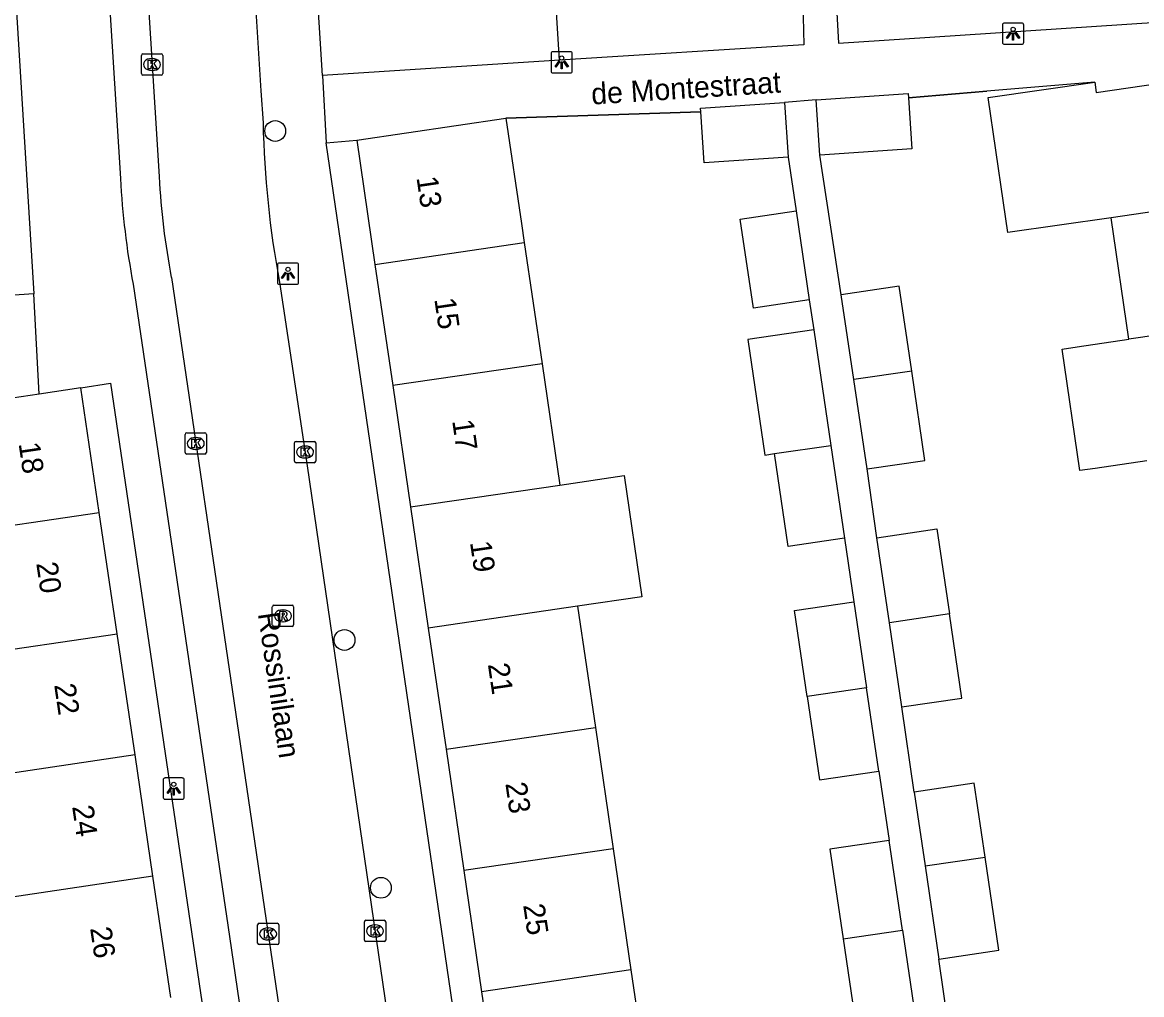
# Model space of a CAD drawing. Extents: x 159053 to 160041, y 380450 to 381422.
# Drawn here: x 159553.7 to 159606.3, y 381083.5 to 381129.1 of the extents above; entities that cross this region are included whole.
import ezdxf

# ---------------------------------------------------------------- set-up
doc = ezdxf.new("R2010")
doc.units = 0
for name, color, linetype in [('IMGEO_Boom', 7, 'Continuous'), ('IMGEO_Groenvoorziening', 7, 'Continuous'), ('IMGEO_Kolk', 7, 'Continuous'), ('IMGEO_Lichtpunt', 7, 'Continuous'), ('IMGEO_Muur', 7, 'Continuous'), ('IMGEO_Openbare_ruimte_label', 7, 'Continuous'), ('IMGEO_Pand', 7, 'Continuous'), ('IMGEO_Pand_nummerreeks', 7, 'Continuous'), ('IMGEO_Rijbaan_lokaal_open', 7, 'Continuous'), ('IMGEO_Rioolput', 7, 'Continuous'), ('IMGEO_Voetpad_op_trap', 7, 'Continuous'), ('IMGEO_Voetpad_open', 7, 'Continuous')]:
    doc.layers.add(name, color=color, linetype=linetype)

msp = doc.modelspace()

# ---------------------------------------------------------------- linework, layer by layer
at = {"layer": 'IMGEO_Boom'}
for centre in [(159565.58, 381124.031), (159568.834, 381100.135), (159570.545, 381088.501)]:
    msp.add_circle(centre, 0.489, dxfattribs=at)
at = {"layer": 'IMGEO_Groenvoorziening'}
msp.add_lwpolyline([(159578.93, 381127.348), (159578.726, 381130.611)], dxfattribs=at)
at = {"layer": 'IMGEO_Kolk'}
for p, q in [((159559.294, 381126.726), (159559.294, 381127.578)), ((159559.369, 381127.652), (159560.221, 381127.652)), ((159559.782, 381127.432), (159559.807, 381127.432)), ((159560.295, 381127.578), (159560.295, 381126.726)), ((159559.805, 381126.872), (159559.78, 381126.872)), ((159560.221, 381126.652), (159559.369, 381126.652)), ((159561.348, 381108.936), (159561.348, 381109.788)), ((159561.423, 381109.862), (159562.275, 381109.862)), ((159561.836, 381109.642), (159561.861, 381109.642)), ((159562.349, 381109.788), (159562.349, 381108.936)), ((159566.557, 381109.458), (159567.409, 381109.458)), ((159561.859, 381109.082), (159561.834, 381109.082)), ((159566.482, 381108.532), (159566.482, 381109.384)), ((159566.97, 381109.238), (159566.995, 381109.238)), ((159567.483, 381109.384), (159567.483, 381108.532)), ((159562.275, 381108.862), (159561.423, 381108.862)), ((159567.409, 381108.458), (159566.557, 381108.458)), ((159566.993, 381108.678), (159566.968, 381108.678)), ((159564.824, 381086.833), (159565.676, 381086.833)), ((159569.769, 381086.048), (159569.769, 381086.9)), ((159569.844, 381086.974), (159570.696, 381086.974)), ((159570.77, 381086.9), (159570.77, 381086.048)), ((159564.749, 381085.907), (159564.749, 381086.759)), ((159565.237, 381086.613), (159565.262, 381086.613)), ((159565.75, 381086.759), (159565.75, 381085.907)), ((159570.257, 381086.754), (159570.282, 381086.754)), ((159565.676, 381085.833), (159564.824, 381085.833)), ((159565.26, 381086.053), (159565.235, 381086.053)), ((159570.696, 381085.974), (159569.844, 381085.974)), ((159570.28, 381086.194), (159570.255, 381086.194))]:
    msp.add_line(p, q, dxfattribs=at)
for points in [[(159559.294, 381126.726), (159559.294, 381127.578)], [(159559.369, 381127.652), (159560.221, 381127.652)], [(159559.615, 381127.352), (159559.738, 381127.352), (159559.738, 381127.201), (159559.868, 381127.352), (159560.032, 381127.352), (159559.886, 381127.201), (159560.039, 381126.952), (159559.887, 381126.952), (159559.802, 381127.116), (159559.738, 381127.049), (159559.738, 381126.952), (159559.615, 381126.952), (159559.615, 381127.352)], [(159560.295, 381127.578), (159560.295, 381126.726)], [(159560.221, 381126.652), (159559.369, 381126.652)], [(159561.348, 381108.936), (159561.348, 381109.788)], [(159561.423, 381109.862), (159562.275, 381109.862)], [(159561.669, 381109.562), (159561.792, 381109.562), (159561.792, 381109.411), (159561.922, 381109.562), (159562.086, 381109.562), (159561.94, 381109.411), (159562.093, 381109.162), (159561.941, 381109.162), (159561.856, 381109.326), (159561.792, 381109.259), (159561.792, 381109.162), (159561.669, 381109.162), (159561.669, 381109.562)], [(159562.349, 381109.788), (159562.349, 381108.936)], [(159566.557, 381109.458), (159567.409, 381109.458)], [(159566.482, 381108.532), (159566.482, 381109.384)], [(159566.803, 381109.158), (159566.926, 381109.158), (159566.926, 381109.007), (159567.056, 381109.158), (159567.22, 381109.158), (159567.074, 381109.007), (159567.227, 381108.758), (159567.075, 381108.758), (159566.99, 381108.922), (159566.926, 381108.855), (159566.926, 381108.758), (159566.803, 381108.758), (159566.803, 381109.158)], [(159567.483, 381109.384), (159567.483, 381108.532)], [(159562.275, 381108.862), (159561.423, 381108.862)], [(159567.409, 381108.458), (159566.557, 381108.458)], [(159564.824, 381086.833), (159565.676, 381086.833)], [(159569.769, 381086.048), (159569.769, 381086.9)], [(159569.844, 381086.974), (159570.696, 381086.974)], [(159570.77, 381086.9), (159570.77, 381086.048)], [(159564.749, 381085.907), (159564.749, 381086.759)], [(159565.07, 381086.533), (159565.193, 381086.533), (159565.193, 381086.382), (159565.323, 381086.533), (159565.487, 381086.533), (159565.341, 381086.382), (159565.494, 381086.133), (159565.342, 381086.133), (159565.257, 381086.297), (159565.193, 381086.23), (159565.193, 381086.133), (159565.07, 381086.133), (159565.07, 381086.533)], [(159565.75, 381086.759), (159565.75, 381085.907)], [(159570.09, 381086.674), (159570.213, 381086.674), (159570.213, 381086.523), (159570.343, 381086.674), (159570.507, 381086.674), (159570.361, 381086.523), (159570.514, 381086.274), (159570.362, 381086.274), (159570.277, 381086.438), (159570.213, 381086.371), (159570.213, 381086.274), (159570.09, 381086.274), (159570.09, 381086.674)], [(159565.676, 381085.833), (159564.824, 381085.833)], [(159570.696, 381085.974), (159569.844, 381085.974)]]:
    msp.add_lwpolyline(points, dxfattribs=at)
for centre, start, end in [((159559.371, 381127.576), 91.552, 178.448), ((159559.371, 381127.576), 91.552, 178.448), ((159560.219, 381127.576), 1.552, 88.448), ((159560.219, 381127.576), 1.552, 88.448), ((159559.371, 381126.728), 181.552, 268.448), ((159559.371, 381126.728), 181.552, 268.448), ((159560.219, 381126.728), 271.552, 358.448), ((159560.219, 381126.728), 271.552, 358.448), ((159561.425, 381109.786), 91.552, 178.448), ((159561.425, 381109.786), 91.552, 178.448), ((159562.273, 381109.786), 1.552, 88.448), ((159562.273, 381109.786), 1.552, 88.448), ((159566.559, 381109.382), 91.552, 178.448), ((159566.559, 381109.382), 91.552, 178.448), ((159567.407, 381109.382), 1.552, 88.448), ((159567.407, 381109.382), 1.552, 88.448), ((159561.425, 381108.938), 181.552, 268.448), ((159561.425, 381108.938), 181.552, 268.448), ((159562.273, 381108.938), 271.552, 358.448), ((159562.273, 381108.938), 271.552, 358.448), ((159566.559, 381108.534), 181.552, 268.448), ((159566.559, 381108.534), 181.552, 268.448), ((159567.407, 381108.534), 271.552, 358.448), ((159567.407, 381108.534), 271.552, 358.448), ((159564.826, 381086.757), 91.552, 178.448), ((159564.826, 381086.757), 91.552, 178.448), ((159565.674, 381086.757), 1.552, 88.448), ((159565.674, 381086.757), 1.552, 88.448), ((159569.846, 381086.898), 91.552, 178.448), ((159569.846, 381086.898), 91.552, 178.448), ((159570.694, 381086.898), 1.552, 88.448), ((159570.694, 381086.898), 1.552, 88.448), ((159564.826, 381085.909), 181.552, 268.448), ((159564.826, 381085.909), 181.552, 268.448), ((159565.674, 381085.909), 271.552, 358.448), ((159565.674, 381085.909), 271.552, 358.448), ((159569.846, 381086.05), 181.552, 268.448), ((159569.846, 381086.05), 181.552, 268.448), ((159570.694, 381086.05), 271.552, 358.448), ((159570.694, 381086.05), 271.552, 358.448)]:
    msp.add_arc(centre, 0.0765, start, end, dxfattribs=at)
for centre, major_axis, ratio, start_param, end_param in [((159559.781, 381127.152), (-0.387, 0.002), 0.722429, 4.712389, 7.853982), ((159559.806, 381127.152), (-0.39, 0.002), 0.717154, 1.570796, 4.712389), ((159561.835, 381109.362), (-0.387, 0.002), 0.722429, 4.712389, 7.853982), ((159561.86, 381109.362), (-0.39, 0.002), 0.717154, 1.570796, 4.712389), ((159566.969, 381108.958), (-0.387, 0.002), 0.722429, 4.712389, 7.853982), ((159566.994, 381108.958), (-0.39, 0.002), 0.717154, 1.570796, 4.712389), ((159565.236, 381086.333), (-0.387, 0.002), 0.722429, 4.712389, 7.853982), ((159565.261, 381086.333), (-0.39, 0.002), 0.717154, 1.570796, 4.712389), ((159570.256, 381086.474), (-0.387, 0.002), 0.722429, 4.712389, 7.853982), ((159570.281, 381086.474), (-0.39, 0.002), 0.717154, 1.570796, 4.712389)]:
    msp.add_ellipse(centre, major_axis=major_axis, ratio=ratio, start_param=start_param, end_param=end_param, dxfattribs=at)
at = {"layer": 'IMGEO_Lichtpunt'}
for p, q in [((159599.743, 381129.004), (159599.743, 381128.197)), ((159599.743, 381129.004), (159599.743, 381128.197)), ((159600.645, 381129.099), (159599.837, 381129.099)), ((159600.645, 381129.099), (159599.837, 381129.099)), ((159600.739, 381128.197), (159600.739, 381129.004)), ((159600.739, 381128.197), (159600.739, 381129.004)), ((159599.837, 381128.103), (159600.645, 381128.103)), ((159599.837, 381128.103), (159600.645, 381128.103)), ((159578.538, 381127.658), (159578.538, 381126.851)), ((159578.538, 381127.658), (159578.538, 381126.851)), ((159579.44, 381127.753), (159578.632, 381127.753)), ((159579.44, 381127.753), (159578.632, 381127.753)), ((159579.534, 381126.851), (159579.534, 381127.658)), ((159579.534, 381126.851), (159579.534, 381127.658)), ((159578.632, 381126.757), (159579.44, 381126.757)), ((159578.632, 381126.757), (159579.44, 381126.757)), ((159566.584, 381117.831), (159565.776, 381117.831)), ((159566.584, 381117.831), (159565.776, 381117.831)), ((159565.682, 381117.736), (159565.682, 381116.929)), ((159565.682, 381117.736), (159565.682, 381116.929)), ((159566.678, 381116.929), (159566.678, 381117.736)), ((159566.678, 381116.929), (159566.678, 381117.736)), ((159565.776, 381116.835), (159566.584, 381116.835)), ((159565.776, 381116.835), (159566.584, 381116.835)), ((159561.216, 381093.655), (159560.408, 381093.655)), ((159561.216, 381093.655), (159560.408, 381093.655)), ((159560.314, 381093.56), (159560.314, 381092.753)), ((159560.314, 381093.56), (159560.314, 381092.753)), ((159561.31, 381092.753), (159561.31, 381093.56)), ((159561.31, 381092.753), (159561.31, 381093.56)), ((159560.408, 381092.659), (159561.216, 381092.659)), ((159560.408, 381092.659), (159561.216, 381092.659))]:
    msp.add_line(p, q, dxfattribs=at)
for points in [[(159600.117, 381128.668), (159600.156, 381128.64), (159599.968, 381128.378), (159599.93, 381128.405), (159600.117, 381128.668)], [(159600.219, 381128.62), (159600.266, 381128.62), (159600.266, 381128.298), (159600.219, 381128.298), (159600.219, 381128.62)], [(159600.329, 381128.64), (159600.367, 381128.667), (159600.554, 381128.405), (159600.515, 381128.377), (159600.329, 381128.64)], [(159578.912, 381127.322), (159578.951, 381127.294), (159578.763, 381127.032), (159578.725, 381127.059), (159578.912, 381127.322)], [(159579.124, 381127.294), (159579.162, 381127.321), (159579.349, 381127.059), (159579.31, 381127.031), (159579.124, 381127.294)], [(159579.014, 381127.274), (159579.061, 381127.274), (159579.061, 381126.952), (159579.014, 381126.952), (159579.014, 381127.274)], [(159566.056, 381117.4), (159566.095, 381117.372), (159565.907, 381117.11), (159565.869, 381117.137), (159566.056, 381117.4)], [(159566.158, 381117.352), (159566.205, 381117.352), (159566.205, 381117.03), (159566.158, 381117.03), (159566.158, 381117.352)], [(159566.268, 381117.372), (159566.306, 381117.399), (159566.493, 381117.137), (159566.454, 381117.109), (159566.268, 381117.372)], [(159560.688, 381093.224), (159560.727, 381093.196), (159560.539, 381092.934), (159560.501, 381092.961), (159560.688, 381093.224)], [(159560.79, 381093.176), (159560.837, 381093.176), (159560.837, 381092.854), (159560.79, 381092.854), (159560.79, 381093.176)], [(159560.9, 381093.196), (159560.938, 381093.223), (159561.125, 381092.961), (159561.086, 381092.933), (159560.9, 381093.196)]]:
    msp.add_lwpolyline(points, dxfattribs=at)
for centre in [(159600.242, 381128.802), (159579.037, 381127.456), (159566.181, 381117.534), (159560.813, 381093.358)]:
    msp.add_circle(centre, 0.0994, dxfattribs=at)
for centre, start, end in [((159599.837, 381129.004), 90, 180), ((159599.837, 381129.004), 90, 180), ((159600.645, 381129.004), 0, 90), ((159600.645, 381129.004), 0, 90), ((159599.837, 381128.197), 180, 270), ((159599.837, 381128.197), 180, 270), ((159600.645, 381128.197), 270, 0), ((159600.645, 381128.197), 270, 360), ((159578.632, 381127.658), 90, 180), ((159578.632, 381127.658), 90, 180), ((159579.44, 381127.658), 0, 90), ((159579.44, 381127.658), 0, 90), ((159578.632, 381126.851), 180, 270), ((159578.632, 381126.851), 180, 270), ((159579.44, 381126.851), 270, 0), ((159579.44, 381126.851), 270, 360), ((159565.776, 381117.736), 90, 180), ((159565.776, 381117.736), 90, 180), ((159566.584, 381117.736), 0, 90), ((159566.584, 381117.736), 0, 90), ((159565.776, 381116.929), 180, 270), ((159565.776, 381116.929), 180, 270), ((159566.584, 381116.929), 270, 0), ((159566.584, 381116.929), 270, 360), ((159560.408, 381093.56), 90, 180), ((159560.408, 381093.56), 90, 180), ((159561.216, 381093.56), 0, 90), ((159561.216, 381093.56), 0, 90), ((159560.408, 381092.753), 180, 270), ((159560.408, 381092.753), 180, 270), ((159561.216, 381092.753), 270, 0), ((159561.216, 381092.753), 270, 360)]:
    msp.add_arc(centre, 0.0946, start, end, dxfattribs=at)
at = {"layer": 'IMGEO_Muur'}
for points in [[(159595.327, 381125.589), (159599.007, 381125.9)], [(159576.42, 381124.632), (159585.571, 381124.935)]]:
    msp.add_lwpolyline(points, dxfattribs=at)
at = {"layer": 'IMGEO_Pand'}
for points in [[(159604.072, 381126.328), (159604.144, 381125.833), (159611.02, 381126.842)], [(159604.847, 381119.956), (159599.997, 381119.269), (159599.795, 381120.655), (159599.075, 381125.602), (159604.072, 381126.328)], [(159590.986, 381125.495), (159595.314, 381125.787), (159595.327, 381125.589)], [(159585.571, 381124.935), (159585.56, 381125.105), (159589.502, 381125.371)], [(159589.502, 381125.371), (159589.676, 381122.794)], [(159591.162, 381122.899), (159590.986, 381125.495)], [(159595.327, 381125.589), (159595.49, 381123.192), (159591.162, 381122.899)], [(159589.676, 381122.794), (159585.734, 381122.528), (159585.571, 381124.935)], [(159569.409, 381123.603), (159576.42, 381124.632)], [(159576.42, 381124.632), (159577.146, 381119.685), (159577.277, 381118.791)], [(159569.409, 381123.603), (159570.265, 381117.766)], [(159611.879, 381120.986), (159604.847, 381119.956)], [(159590.666, 381116.096), (159588.04, 381115.707), (159587.422, 381119.891), (159590.048, 381120.279)], [(159590.048, 381120.279), (159590.666, 381116.096)], [(159605.684, 381114.25), (159604.847, 381119.956)], [(159570.265, 381117.766), (159577.277, 381118.791)], [(159577.277, 381118.791), (159578.112, 381113.1)], [(159570.265, 381117.766), (159571.101, 381112.075)], [(159595.48, 381112.756), (159594.894, 381116.748), (159592.17, 381116.345)], [(159592.76, 381112.357), (159592.17, 381116.345)], [(159612.716, 381115.28), (159605.684, 381114.25)], [(159590.88, 381114.699), (159587.783, 381114.244), (159588.579, 381108.818), (159589.032, 381108.883)], [(159590.88, 381114.699), (159591.676, 381109.27)], [(159606.521, 381108.544), (159604.092, 381108.188), (159603.381, 381108.084), (159602.544, 381113.79), (159603.255, 381113.894), (159605.684, 381114.25)], [(159578.112, 381113.1), (159571.101, 381112.075)], [(159578.112, 381113.1), (159578.947, 381107.409)], [(159595.48, 381112.756), (159592.76, 381112.357)], [(159593.379, 381108.17), (159596.094, 381108.568), (159595.48, 381112.756)], [(159571.101, 381112.075), (159571.936, 381106.384)], [(159593.379, 381108.17), (159592.76, 381112.357)], [(159554.494, 381111.677), (159549.41, 381110.926)], [(159556.453, 381111.966), (159554.494, 381111.677)], [(159557.316, 381106.124), (159556.453, 381111.966)], [(159589.032, 381108.883), (159591.676, 381109.27)], [(159592.319, 381104.918), (159589.676, 381104.527), (159589.032, 381108.883)], [(159591.676, 381109.27), (159592.319, 381104.918)], [(159578.947, 381107.409), (159581.968, 381107.851), (159582.8, 381102.158), (159579.782, 381101.717)], [(159571.936, 381106.384), (159578.947, 381107.409)], [(159571.936, 381106.384), (159572.771, 381100.693)], [(159550.272, 381105.084), (159557.316, 381106.124)], [(159558.156, 381100.43), (159557.316, 381106.124)], [(159593.845, 381104.934), (159596.663, 381105.351), (159597.253, 381101.357)], [(159594.435, 381100.944), (159593.845, 381104.934)], [(159579.782, 381101.717), (159572.771, 381100.693)], [(159579.782, 381101.717), (159580.617, 381096.027)], [(159590.571, 381097.482), (159589.975, 381101.515), (159592.761, 381101.927)], [(159592.761, 381101.927), (159593.359, 381097.89)], [(159597.253, 381101.357), (159594.435, 381100.944)], [(159595.02, 381096.988), (159597.838, 381097.405), (159597.253, 381101.357)], [(159572.771, 381100.693), (159573.606, 381095.002)], [(159595.02, 381096.988), (159594.435, 381100.944)], [(159551.113, 381099.39), (159558.156, 381100.43)], [(159558.997, 381094.737), (159558.156, 381100.43)], [(159593.359, 381097.89), (159590.571, 381097.482)], [(159593.937, 381093.982), (159593.359, 381097.89)], [(159590.571, 381097.482), (159591.149, 381093.574), (159593.937, 381093.982)], [(159573.606, 381095.002), (159580.617, 381096.027)], [(159580.617, 381096.027), (159581.452, 381090.336)], [(159558.997, 381094.737), (159551.954, 381093.697)], [(159559.838, 381089.044), (159558.997, 381094.737)], [(159573.606, 381095.002), (159574.441, 381089.31)], [(159598.927, 381089.944), (159598.415, 381093.413), (159595.597, 381092.996)], [(159595.597, 381092.996), (159596.109, 381089.531)], [(159594.418, 381090.723), (159591.631, 381090.315), (159592.254, 381086.102)], [(159595.041, 381086.51), (159594.418, 381090.723)], [(159581.452, 381090.336), (159574.441, 381089.31)], [(159581.452, 381090.336), (159582.287, 381084.645)], [(159596.109, 381089.531), (159598.927, 381089.944)], [(159596.109, 381089.531), (159596.756, 381085.155)], [(159596.756, 381085.155), (159599.574, 381085.572), (159598.927, 381089.944)], [(159559.838, 381089.044), (159552.794, 381088.004)], [(159560.678, 381083.351), (159559.838, 381089.044)], [(159574.441, 381089.31), (159575.276, 381083.62)], [(159592.254, 381086.102), (159595.041, 381086.51)], [(159595.041, 381086.51), (159595.639, 381082.47)], [(159592.254, 381086.102), (159592.851, 381082.063), (159595.639, 381082.47)], [(159582.287, 381084.645), (159575.276, 381083.62)], [(159582.287, 381084.645), (159583.123, 381078.953)], [(159575.276, 381083.62), (159576.111, 381077.928)]]:
    msp.add_lwpolyline(points, dxfattribs=at)
at = {"layer": 'IMGEO_Rijbaan_lokaal_open'}
for points in [[(159559.09, 381138.351), (159560.128, 381121.887)], [(159564.1, 381138.669), (159564.624, 381130.435), (159564.912, 381125.915), (159565.008, 381124.407)], [(159560.701, 381117.152), (159566.872, 381075.271)], [(159565.779, 381116.931), (159567.081, 381108.31), (159571.387, 381078.814), (159571.803, 381076)]]:
    msp.add_lwpolyline(points, dxfattribs=at)
for centre, radius, start, end in [((159612.375, 381125.514), 47.38, 181.3391, 190.4371), ((159595.633, 381123.781), 35.556, 183.0542, 190.7458)]:
    msp.add_arc(centre, radius, start, end, dxfattribs=at)
at = {"layer": 'IMGEO_Rioolput'}
for p, q in [((159565.445, 381100.843), (159565.445, 381101.695)), ((159565.52, 381101.769), (159566.372, 381101.769)), ((159565.933, 381101.549), (159565.958, 381101.549)), ((159566.446, 381101.695), (159566.446, 381100.843)), ((159566.372, 381100.769), (159565.52, 381100.769)), ((159565.956, 381100.989), (159565.931, 381100.989))]:
    msp.add_line(p, q, dxfattribs=at)
for points in [[(159565.445, 381100.843), (159565.445, 381101.695)], [(159565.52, 381101.769), (159566.372, 381101.769)], [(159566.446, 381101.695), (159566.446, 381100.843)], [(159566.034, 381101.467), (159565.782, 381101.469), (159565.782, 381101.069)], [(159565.782, 381101.069), (159565.906, 381101.069), (159565.906, 381101.231), (159565.917, 381101.231)], [(159565.96, 381101.388), (159565.906, 381101.388), (159565.906, 381101.307)], [(159565.906, 381101.307), (159565.958, 381101.307)], [(159565.964, 381101.202), (159566.035, 381101.069), (159566.175, 381101.069), (159566.11, 381101.195)], [(159566.372, 381100.769), (159565.52, 381100.769)]]:
    msp.add_lwpolyline(points, dxfattribs=at)
for centre, radius, start, end in [((159565.522, 381101.693), 0.0765, 91.552, 178.448), ((159565.522, 381101.693), 0.0765, 91.552, 178.448), ((159566.37, 381101.693), 0.0765, 1.552, 88.448), ((159566.37, 381101.693), 0.0765, 1.552, 88.448), ((159565.916, 381101.178), 0.0533, 26.0293, 88.6989), ((159565.942, 381101.496), 0.19, 274.7715, 282.9687), ((159565.966, 381101.292), 0.0964, 77.0061, 93.1865), ((159565.98, 381101.349), 0.0378, 276.6634, 79.6772), ((159566.033, 381101.357), 0.109, 350.3612, 89.416), ((159566.031, 381101.357), 0.112, 277.5842, 350.9817), ((159566.015, 381101.142), 0.108, 29.5134, 73.7905), ((159565.522, 381100.845), 0.0765, 181.552, 268.448), ((159565.522, 381100.845), 0.0765, 181.552, 268.448), ((159566.37, 381100.845), 0.0765, 271.552, 358.448), ((159566.37, 381100.845), 0.0765, 271.552, 358.448)]:
    msp.add_arc(centre, radius, start, end, dxfattribs=at)
for centre, major_axis, ratio, start_param, end_param in [((159565.932, 381101.269), (-0.387, 0.002), 0.722429, 4.712389, 7.853982), ((159565.957, 381101.269), (-0.39, 0.002), 0.717154, 1.570796, 4.712389)]:
    msp.add_ellipse(centre, major_axis=major_axis, ratio=ratio, start_param=start_param, end_param=end_param, dxfattribs=at)
at = {"layer": 'IMGEO_Voetpad_op_trap'}
for points in [[(159550.971, 381169.356), (159554.244, 381116.384)], [(159555.451, 381167.62), (159556.106, 381156.762), (159558.311, 381121.794)], [(159558.908, 381116.837), (159563.427, 381086.22), (159569.973, 381041.563), (159574.048, 381013.707), (159574.57, 381010.14), (159576.089, 381000), (159576.625, 380995.481), (159576.807, 380993.975)], [(159556.453, 381111.966), (159557.841, 381112.195), (159572.181, 381015.08), (159570.79, 381014.875)]]:
    msp.add_lwpolyline(points, dxfattribs=at)
msp.add_arc((159594.9, 381123.686), 36.638, 182.9603, 190.7744, dxfattribs=at)
at = {"layer": 'IMGEO_Voetpad_open'}
for points in [[(159567.796, 381126.635), (159565.061, 381170.206)], [(159591.847, 381131.564), (159592.04, 381128.159), (159596.333, 381128.442), (159608.66, 381129.256), (159608.578, 381131.566)], [(159590.335, 381131.38), (159590.41, 381128.083), (159578.93, 381127.348)], [(159578.93, 381127.348), (159567.796, 381126.635)], [(159567.796, 381126.635), (159567.971, 381123.474)], [(159604.072, 381126.328), (159599.007, 381125.9), (159595.327, 381125.589)], [(159590.986, 381125.495), (159589.502, 381125.371)], [(159585.571, 381124.935), (159576.42, 381124.632)], [(159567.971, 381123.474), (159569.409, 381123.603)], [(159585.319, 381015.173), (159583.892, 381014.966), (159567.971, 381123.474)], [(159589.676, 381122.794), (159590.048, 381120.279)], [(159592.17, 381116.345), (159591.162, 381122.899)], [(159554.244, 381116.384), (159551.022, 381116.161)], [(159554.494, 381111.677), (159554.244, 381116.384)], [(159590.666, 381116.096), (159590.88, 381114.699)], [(159593.845, 381104.934), (159593.379, 381108.17)], [(159592.319, 381104.918), (159592.761, 381101.927)], [(159595.597, 381092.996), (159595.02, 381096.988)], [(159593.937, 381093.982), (159594.418, 381090.723)], [(159597.194, 381082.109), (159596.756, 381085.155)]]:
    msp.add_lwpolyline(points, dxfattribs=at)

# ---------------------------------------------------------------- texts
at = {"layer": 'IMGEO_Openbare_ruimte_label'}
for s, rotation, p in [('de Montestraat', 3.6693, (159580.455, 381125.268)), ('Rossinilaan', 278.3976, (159564.763, 381101.372))]:
    msp.add_text(s, height=1, rotation=rotation, dxfattribs=at).set_placement(p)
at = {"layer": 'IMGEO_Pand_nummerreeks'}
for s, rotation, p in [('13', 278.3475, (159572.214, 381121.843)), ('15', 278.3475, (159573.051, 381116.136)), ('17', 278.3475, (159573.889, 381110.429)), ('18', 278.3994, (159553.523, 381109.356)), ('19', 278.3475, (159574.726, 381104.722)), ('20', 278.3999, (159554.353, 381103.735)), ('21', 278.3475, (159575.566, 381098.994)), ('22', 278.3999, (159555.195, 381098.029)), ('23', 278.3475, (159576.388, 381093.398)), ('24', 278.3999, (159556.039, 381092.315)), ('25', 278.3475, (159577.225, 381087.692)), ('26', 278.3999, (159556.882, 381086.604))]:
    msp.add_text(s, height=1, rotation=rotation, dxfattribs=at).set_placement(p)

doc.saveas('drawing.dxf')
